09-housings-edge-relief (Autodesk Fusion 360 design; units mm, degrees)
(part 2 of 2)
sketch "B Facet 180 Triangle 4" plane through (0, -75, 0) normal (0, -1, 0) x axis (-1, 0, 0)
  line L1 (124, -27.066) -> (60.9665, 27.066)
  line L2 (124, 27.066) -> (124, -27.066)
  line L3 (60.9665, 27.066) -> (124, 27.066)
  line L4 (120, -18.3583) -> (71.7639, 23.066)
  line L5 (120, 23.066) -> (120, -18.3583)
  line L6 (71.7639, 23.066) -> (120, 23.066)
  point P1 (0, 0)
  point P2 (60.9665, 27.066)
  point P3 (124, -27.066)
  point P4 (124, 27.066)
  dimension "d486" distance P1 P2 = 60.9665 (= "Linear Dimension-2")
  dimension "d487" distance P1 P2 = 27.066 (= "Linear Dimension-3")
  dimension "d488" distance P1 P3 = 124 (= "Linear Dimension-4")
  dimension "d489" distance P1 P3 = 27.066 (= "Linear Dimension-5")
  dimension "d490" distance P1 P4 = 124 (= "Linear Dimension-6")
  dimension "d491" distance P1 P4 = 27.066 (= "Linear Dimension-7")
  dimension "d492" = -4 (= "-memberWidth / 2")
extrude "Extrude15" cut sketch "B Facet 180 Triangle 4" profile of L5 L6 L4 against normal blind 4.7 (magnitude of "-( wall + 0.2 mm )")
fillet "Fillet5" radius 1.5 (= "apertureRadius")
work_plane "WorkPlane11" RotateAngle 135 ExtraOffset 0
work_plane "WorkPlane12" AlongDistance 75 (= "bodyWidth / 2") ExtraOffset 0
sketch "B Facet 225 Triangle 1" plane through (0, -53.033, -53.033) normal (0, -0.7071, -0.7071) x axis (1, 0, 0)
  line L1 (23.9949, -27.066) -> (62.2721, 27.066)
  line L2 (0.1814, 27.066) -> (23.9949, -27.066)
  line L3 (62.2721, 27.066) -> (0.1814, 27.066)
  line L4 (24.81, -18.9852) -> (54.5447, 23.066)
  line L5 (6.311, 23.066) -> (24.81, -18.9852)
  line L6 (54.5447, 23.066) -> (6.311, 23.066)
  point P1 (0, 0)
  point P2 (62.2721, 27.066)
  point P3 (23.9949, -27.066)
  point P4 (0.1814, 27.066)
  dimension "d501" distance P1 P2 = 62.2721 (= "Linear Dimension-2")
  dimension "d502" distance P1 P2 = 27.066 (= "Linear Dimension-3")
  dimension "d503" distance P1 P3 = 23.9949 (= "Linear Dimension-4")
  dimension "d504" distance P1 P3 = 27.066 (= "Linear Dimension-5")
  dimension "d505" distance P1 P4 = 0.1814 (= "Linear Dimension-6")
  dimension "d506" distance P1 P4 = 27.066 (= "Linear Dimension-7")
  dimension "d507" = 4 (= "memberWidth / 2")
extrude "Extrude16" cut sketch "B Facet 225 Triangle 1" profile of L5 L6 L4 against normal blind 4.7 (magnitude of "-( wall + 0.2 mm )")
sketch "B Facet 225 Triangle 2" plane through (0, -53.033, -53.033) normal (0, -0.7071, -0.7071) x axis (1, 0, 0)
  line L1 (0.1814, 27.066) -> (23.9949, -27.066)
  line L2 (-74.6684, -27.066) -> (0.1814, 27.066)
  line L3 (23.9949, -27.066) -> (-74.6684, -27.066)
  line L4 (-1.4863, 20.9235) -> (17.8653, -23.066)
  line L5 (-62.3117, -23.066) -> (-1.4863, 20.9235)
  line L6 (17.8653, -23.066) -> (-62.3117, -23.066)
  point P1 (0, 0)
  point P2 (23.9949, -27.066)
  point P3 (0.1814, 27.066)
  point P4 (-74.6684, -27.066)
  dimension "d510" distance P1 P2 = 23.9949 (= "Linear Dimension-2")
  dimension "d511" distance P1 P2 = 27.066 (= "Linear Dimension-3")
  dimension "d512" distance P1 P3 = 0.1814 (= "Linear Dimension-4")
  dimension "d513" distance P1 P3 = 27.066 (= "Linear Dimension-5")
  dimension "d514" distance P1 P4 = 74.6684 (= "Linear Dimension-6")
  dimension "d515" distance P1 P4 = 27.066 (= "Linear Dimension-7")
  dimension "d516" = -4 (= "-memberWidth / 2")
extrude "Extrude17" cut sketch "B Facet 225 Triangle 2" profile of L5 L6 L4 against normal blind 4.7 (magnitude of "-( wall + 0.2 mm )")
sketch "B Facet 225 Triangle 3" plane through (0, -53.033, -53.033) normal (0, -0.7071, -0.7071) x axis (1, 0, 0)
  line L1 (-74.6684, -27.066) -> (0.1814, 27.066)
  line L2 (-124, 27.066) -> (-74.6684, -27.066)
  line L3 (0.1814, 27.066) -> (-124, 27.066)
  line L4 (-74.1179, -21.7315) -> (-12.1753, 23.066)
  line L5 (-114.9429, 23.066) -> (-74.1179, -21.7315)
  line L6 (-12.1753, 23.066) -> (-114.9429, 23.066)
  point P1 (0, 0)
  point P2 (0.1814, 27.066)
  point P3 (-74.6684, -27.066)
  point P4 (-124, 27.066)
  dimension "d519" distance P1 P2 = 0.1814 (= "Linear Dimension-2")
  dimension "d520" distance P1 P2 = 27.066 (= "Linear Dimension-3")
  dimension "d521" distance P1 P3 = 74.6684 (= "Linear Dimension-4")
  dimension "d522" distance P1 P3 = 27.066 (= "Linear Dimension-5")
  dimension "d523" distance P1 P4 = 124 (= "Linear Dimension-6")
  dimension "d524" distance P1 P4 = 27.066 (= "Linear Dimension-7")
  dimension "d525" = 4 (= "memberWidth / 2")
extrude "Extrude18" cut sketch "B Facet 225 Triangle 3" profile of L5 L6 L4 against normal blind 4.7 (magnitude of "-( wall + 0.2 mm )")
sketch "B Facet 225 Triangle 4" plane through (0, -53.033, -53.033) normal (0, -0.7071, -0.7071) x axis (1, 0, 0)
  line L1 (-124, 27.066) -> (-74.6684, -27.066)
  line L2 (-124, -27.066) -> (-124, 27.066)
  line L3 (-74.6684, -27.066) -> (-124, -27.066)
  line L4 (-120, 16.7383) -> (-83.7255, -23.066)
  line L5 (-120, -23.066) -> (-120, 16.7383)
  line L6 (-83.7255, -23.066) -> (-120, -23.066)
  point P1 (0, 0)
  point P2 (-74.6684, -27.066)
  point P3 (-124, 27.066)
  point P4 (-124, -27.066)
  dimension "d528" distance P1 P2 = 74.6684 (= "Linear Dimension-2")
  dimension "d529" distance P1 P2 = 27.066 (= "Linear Dimension-3")
  dimension "d530" distance P1 P3 = 124 (= "Linear Dimension-4")
  dimension "d531" distance P1 P3 = 27.066 (= "Linear Dimension-5")
  dimension "d532" distance P1 P4 = 124 (= "Linear Dimension-6")
  dimension "d533" distance P1 P4 = 27.066 (= "Linear Dimension-7")
  dimension "d534" = -4 (= "-memberWidth / 2")
extrude "Extrude19" cut sketch "B Facet 225 Triangle 4" profile of L5 L6 L4 against normal blind 4.7 (magnitude of "-( wall + 0.2 mm )")
fillet "Fillet6" radius 1.5 (= "apertureRadius")
work_plane "WorkPlane13" RotateAngle 180 ExtraOffset 0
work_plane "WorkPlane14" AlongDistance 75 (= "bodyWidth / 2") ExtraOffset 0
sketch "B Facet 270 Triangle 1" plane through (0, 0, -75) normal (0, 0, -1) x axis (-1, 0, 0)
  line L1 (36.9655, 27.066) -> (-17.1665, -27.066)
  line L2 (53.4167, -27.066) -> (36.9655, 27.066)
  line L3 (-17.1665, -27.066) -> (53.4167, -27.066)
  line L4 (35.0777, 19.5214) -> (-7.5097, -23.066)
  line L5 (48.0205, -23.066) -> (35.0777, 19.5214)
  line L6 (-7.5097, -23.066) -> (48.0205, -23.066)
  point P1 (0, 0)
  point P2 (-17.1665, -27.066)
  point P3 (36.9655, 27.066)
  point P4 (53.4167, -27.066)
  dimension "d543" distance P1 P2 = 17.1665 (= "Linear Dimension-2")
  dimension "d544" distance P1 P2 = 27.066 (= "Linear Dimension-3")
  dimension "d545" distance P1 P3 = 36.9655 (= "Linear Dimension-4")
  dimension "d546" distance P1 P3 = 27.066 (= "Linear Dimension-5")
  dimension "d547" distance P1 P4 = 53.4167 (= "Linear Dimension-6")
  dimension "d548" distance P1 P4 = 27.066 (= "Linear Dimension-7")
  dimension "d549" = 4 (= "memberWidth / 2")
extrude "Extrude20" cut sketch "B Facet 270 Triangle 1" profile of L5 L6 L4 against normal blind 4.7 (magnitude of "-( wall + 0.2 mm )")
sketch "B Facet 270 Triangle 2" plane through (0, 0, -75) normal (0, 0, -1) x axis (-1, 0, 0)
  line L1 (53.4167, -27.066) -> (36.9655, 27.066)
  line L2 (124, 27.066) -> (53.4167, -27.066)
  line L3 (36.9655, 27.066) -> (124, 27.066)
  line L4 (55.5648, -20.3777) -> (42.3618, 23.066)
  line L5 (112.2115, 23.066) -> (55.5648, -20.3777)
  line L6 (42.3618, 23.066) -> (112.2115, 23.066)
  point P1 (0, 0)
  point P2 (36.9655, 27.066)
  point P3 (53.4167, -27.066)
  point P4 (124, 27.066)
  dimension "d552" distance P1 P2 = 36.9655 (= "Linear Dimension-2")
  dimension "d553" distance P1 P2 = 27.066 (= "Linear Dimension-3")
  dimension "d554" distance P1 P3 = 53.4167 (= "Linear Dimension-4")
  dimension "d555" distance P1 P3 = 27.066 (= "Linear Dimension-5")
  dimension "d556" distance P1 P4 = 124 (= "Linear Dimension-6")
  dimension "d557" distance P1 P4 = 27.066 (= "Linear Dimension-7")
  dimension "d558" = -4 (= "-memberWidth / 2")
extrude "Extrude21" cut sketch "B Facet 270 Triangle 2" profile of L5 L6 L4 against normal blind 4.7 (magnitude of "-( wall + 0.2 mm )")
sketch "B Facet 270 Triangle 3" plane through (0, 0, -75) normal (0, 0, -1) x axis (-1, 0, 0)
  line L1 (124, 27.066) -> (53.4167, -27.066)
  line L2 (124, -27.066) -> (124, 27.066)
  line L3 (53.4167, -27.066) -> (124, -27.066)
  line L4 (120, 18.9574) -> (65.2053, -23.066)
  line L5 (120, -23.066) -> (120, 18.9574)
  line L6 (65.2053, -23.066) -> (120, -23.066)
  point P1 (0, 0)
  point P2 (53.4167, -27.066)
  point P3 (124, 27.066)
  point P4 (124, -27.066)
  dimension "d561" distance P1 P2 = 53.4167 (= "Linear Dimension-2")
  dimension "d562" distance P1 P2 = 27.066 (= "Linear Dimension-3")
  dimension "d563" distance P1 P3 = 124 (= "Linear Dimension-4")
  dimension "d564" distance P1 P3 = 27.066 (= "Linear Dimension-5")
  dimension "d565" distance P1 P4 = 124 (= "Linear Dimension-6")
  dimension "d566" distance P1 P4 = 27.066 (= "Linear Dimension-7")
  dimension "d567" = 4 (= "memberWidth / 2")
extrude "Extrude22" cut sketch "B Facet 270 Triangle 3" profile of L5 L6 L4 against normal blind 4.7 (magnitude of "-( wall + 0.2 mm )")
fillet "Fillet7" radius 1.5 (= "apertureRadius")
work_plane "WorkPlane15" RotateAngle 225 ExtraOffset 0
work_plane "WorkPlane16" AlongDistance 75 (= "bodyWidth / 2") ExtraOffset 0
sketch "B Facet 315 Triangle 1" plane through (0, 53.033, -53.033) normal (0, 0.7071, -0.7071) x axis (1, 0, 0)
  line L1 (-82.0711, -27.066) -> (-43.7939, 27.066)
  line L2 (-124, 27.066) -> (-82.0711, -27.066)
  line L3 (-43.7939, 27.066) -> (-124, 27.066)
  line L4 (-82.2175, -20.3449) -> (-51.5213, 23.066)
  line L5 (-115.8422, 23.066) -> (-82.2175, -20.3449)
  line L6 (-51.5213, 23.066) -> (-115.8422, 23.066)
  point P1 (0, 0)
  point P2 (-43.7939, 27.066)
  point P3 (-82.0711, -27.066)
  point P4 (-124, 27.066)
  dimension "d576" distance P1 P2 = 43.7939 (= "Linear Dimension-2")
  dimension "d577" distance P1 P2 = 27.066 (= "Linear Dimension-3")
  dimension "d578" distance P1 P3 = 82.0711 (= "Linear Dimension-4")
  dimension "d579" distance P1 P3 = 27.066 (= "Linear Dimension-5")
  dimension "d580" distance P1 P4 = 124 (= "Linear Dimension-6")
  dimension "d581" distance P1 P4 = 27.066 (= "Linear Dimension-7")
  dimension "d582" = 4 (= "memberWidth / 2")
extrude "Extrude23" cut sketch "B Facet 315 Triangle 1" profile of L5 L6 L4 against normal blind 4.7 (magnitude of "-( wall + 0.2 mm )")
sketch "B Facet 315 Triangle 2" plane through (0, 53.033, -53.033) normal (0, 0.7071, -0.7071) x axis (1, 0, 0)
  line L1 (-124, 27.066) -> (-82.0711, -27.066)
  line L2 (-124, -27.066) -> (-124, 27.066)
  line L3 (-82.0711, -27.066) -> (-124, -27.066)
  line L4 (-120, 15.3697) -> (-90.2289, -23.066)
  line L5 (-120, -23.066) -> (-120, 15.3697)
  line L6 (-90.2289, -23.066) -> (-120, -23.066)
  point P1 (0, 0)
  point P2 (-82.0711, -27.066)
  point P3 (-124, 27.066)
  point P4 (-124, -27.066)
  dimension "d585" distance P1 P2 = 82.0711 (= "Linear Dimension-2")
  dimension "d586" distance P1 P2 = 27.066 (= "Linear Dimension-3")
  dimension "d587" distance P1 P3 = 124 (= "Linear Dimension-4")
  dimension "d588" distance P1 P3 = 27.066 (= "Linear Dimension-5")
  dimension "d589" distance P1 P4 = 124 (= "Linear Dimension-6")
  dimension "d590" distance P1 P4 = 27.066 (= "Linear Dimension-7")
  dimension "d591" = -4 (= "-memberWidth / 2")
extrude "Extrude24" cut sketch "B Facet 315 Triangle 2" profile of L5 L6 L4 against normal blind 4.7 (magnitude of "-( wall + 0.2 mm )")
fillet "Fillet8" radius 1.5 (= "apertureRadius")
work_plane "WorkPlane17" AlongDistance 0.5 (= "qFront") ExtraOffset 0
sketch "A Central Carrier sketch" plane through (0.3536, 0.3536, 0) normal (0.7071, 0.7071, 0) x axis (0, 0, 1)
  circle C1 centre (0, 0) radius 26
  dimension "d598" diameter C1 = 52 (= "carrierOD")
extrude "Extrude25" new body sketch "A Central Carrier sketch" along normal blind 18 (= "spokeDepth")
work_plane "WorkPlane18" AlongDistance 0.5 (= "qFront") ExtraOffset 0
sketch "A Spoke 1 Profile" plane through (0.3536, 0.3536, 0) normal (0.7071, 0.7071, 0) x axis (0, 0, 1)
  line L1 (37.3643, -145.3579) -> (-4.7984, -1.4054)
  line L2 (46.9611, -142.547) -> (37.3643, -145.3579)
  line L3 (4.7984, 1.4054) -> (46.9611, -142.547)
  line L4 (-4.7984, -1.4054) -> (4.7984, 1.4054)
  point P1 (0, 0)
  point P2 (-4.7984, -1.4054)
  point P3 (37.3643, -145.3579)
  point P4 (46.9611, -142.547)
  point P5 (4.7984, 1.4054)
  dimension "d603" distance P1 P2 = 4.7984 (= "Linear Dimension-2")
  dimension "d604" distance P1 P2 = 1.4054 (= "Linear Dimension-3")
  dimension "d605" distance P1 P3 = 37.3643 (= "Linear Dimension-4")
  dimension "d606" distance P1 P3 = 145.3579 (= "Linear Dimension-5")
  dimension "d607" distance P1 P4 = 46.9611 (= "Linear Dimension-6")
  dimension "d608" distance P1 P4 = 142.547 (= "Linear Dimension-7")
  dimension "d609" distance P1 P5 = 4.7984 (= "Linear Dimension-8")
  dimension "d610" distance P1 P5 = 1.4054 (= "Linear Dimension-9")
extrude "Extrude26" add sketch "A Spoke 1 Profile" along normal blind 18 (= "spokeDepth")
sketch "A Spoke 2 Profile" plane through (0.3536, 0.3536, 0) normal (0.7071, 0.7071, 0) x axis (0, 0, 1)
  line L1 (126.9012, -80.1317) -> (-2.5272, -4.3143)
  line L2 (131.9557, -71.5031) -> (126.9012, -80.1317)
  line L3 (2.5272, 4.3143) -> (131.9557, -71.5031)
  line L4 (-2.5272, -4.3143) -> (2.5272, 4.3143)
  point P1 (0, 0)
  point P2 (-2.5272, -4.3143)
  point P3 (126.9012, -80.1317)
  point P4 (131.9557, -71.5031)
  point P5 (2.5272, 4.3143)
  dimension "d613" distance P1 P2 = 2.5272 (= "Linear Dimension-2")
  dimension "d614" distance P1 P2 = 4.3143 (= "Linear Dimension-3")
  dimension "d615" distance P1 P3 = 126.9012 (= "Linear Dimension-4")
  dimension "d616" distance P1 P3 = 80.1317 (= "Linear Dimension-5")
  dimension "d617" distance P1 P4 = 131.9557 (= "Linear Dimension-6")
  dimension "d618" distance P1 P4 = 71.5031 (= "Linear Dimension-7")
  dimension "d619" distance P1 P5 = 2.5272 (= "Linear Dimension-8")
  dimension "d620" distance P1 P5 = 4.3143 (= "Linear Dimension-9")
extrude "Extrude27" add sketch "A Spoke 2 Profile" along normal blind 18 (= "spokeDepth")
sketch "A Spoke 3 Profile" plane through (0.3536, 0.3536, 0) normal (0.7071, 0.7071, 0) x axis (0, 0, 1)
  line L1 (131.9557, 71.5031) -> (2.5272, -4.3143)
  line L2 (126.9012, 80.1317) -> (131.9557, 71.5031)
  line L3 (-2.5272, 4.3143) -> (126.9012, 80.1317)
  line L4 (2.5272, -4.3143) -> (-2.5272, 4.3143)
  point P1 (0, 0)
  point P2 (2.5272, -4.3143)
  point P3 (131.9557, 71.5031)
  point P4 (126.9012, 80.1317)
  point P5 (-2.5272, 4.3143)
  dimension "d623" distance P1 P2 = 2.5272 (= "Linear Dimension-2")
  dimension "d624" distance P1 P2 = 4.3143 (= "Linear Dimension-3")
  dimension "d625" distance P1 P3 = 131.9557 (= "Linear Dimension-4")
  dimension "d626" distance P1 P3 = 71.5031 (= "Linear Dimension-5")
  dimension "d627" distance P1 P4 = 126.9012 (= "Linear Dimension-6")
  dimension "d628" distance P1 P4 = 80.1317 (= "Linear Dimension-7")
  dimension "d629" distance P1 P5 = 2.5272 (= "Linear Dimension-8")
  dimension "d630" distance P1 P5 = 4.3143 (= "Linear Dimension-9")
extrude "Extrude28" add sketch "A Spoke 3 Profile" along normal blind 18 (= "spokeDepth")
sketch "A Spoke 4 Profile" plane through (0.3536, 0.3536, 0) normal (0.7071, 0.7071, 0) x axis (0, 0, 1)
  line L1 (46.9611, 142.547) -> (4.7984, -1.4054)
  line L2 (37.3643, 145.3579) -> (46.9611, 142.547)
  line L3 (-4.7984, 1.4054) -> (37.3643, 145.3579)
  line L4 (4.7984, -1.4054) -> (-4.7984, 1.4054)
  point P1 (0, 0)
  point P2 (4.7984, -1.4054)
  point P3 (46.9611, 142.547)
  point P4 (37.3643, 145.3579)
  point P5 (-4.7984, 1.4054)
  dimension "d633" distance P1 P2 = 4.7984 (= "Linear Dimension-2")
  dimension "d634" distance P1 P2 = 1.4054 (= "Linear Dimension-3")
  dimension "d635" distance P1 P3 = 46.9611 (= "Linear Dimension-4")
  dimension "d636" distance P1 P3 = 142.547 (= "Linear Dimension-5")
  dimension "d637" distance P1 P4 = 37.3643 (= "Linear Dimension-6")
  dimension "d638" distance P1 P4 = 145.3579 (= "Linear Dimension-7")
  dimension "d639" distance P1 P5 = 4.7984 (= "Linear Dimension-8")
  dimension "d640" distance P1 P5 = 1.4054 (= "Linear Dimension-9")
extrude "Extrude29" add sketch "A Spoke 4 Profile" along normal blind 18 (= "spokeDepth")
sketch "A Spoke 5 Profile" plane through (0.3536, 0.3536, 0) normal (0.7071, 0.7071, 0) x axis (0, 0, 1)
  line L1 (-37.3643, 145.3579) -> (4.7984, 1.4054)
  line L2 (-46.9611, 142.547) -> (-37.3643, 145.3579)
  line L3 (-4.7984, -1.4054) -> (-46.9611, 142.547)
  line L4 (4.7984, 1.4054) -> (-4.7984, -1.4054)
  point P1 (0, 0)
  point P2 (4.7984, 1.4054)
  point P3 (-37.3643, 145.3579)
  point P4 (-46.9611, 142.547)
  point P5 (-4.7984, -1.4054)
  dimension "d643" distance P1 P2 = 4.7984 (= "Linear Dimension-2")
  dimension "d644" distance P1 P2 = 1.4054 (= "Linear Dimension-3")
  dimension "d645" distance P1 P3 = 37.3643 (= "Linear Dimension-4")
  dimension "d646" distance P1 P3 = 145.3579 (= "Linear Dimension-5")
  dimension "d647" distance P1 P4 = 46.9611 (= "Linear Dimension-6")
  dimension "d648" distance P1 P4 = 142.547 (= "Linear Dimension-7")
  dimension "d649" distance P1 P5 = 4.7984 (= "Linear Dimension-8")
  dimension "d650" distance P1 P5 = 1.4054 (= "Linear Dimension-9")
extrude "Extrude30" add sketch "A Spoke 5 Profile" along normal blind 18 (= "spokeDepth")
sketch "A Spoke 6 Profile" plane through (0.3536, 0.3536, 0) normal (0.7071, 0.7071, 0) x axis (0, 0, 1)
  line L1 (-126.9012, 80.1317) -> (2.5272, 4.3143)
  line L2 (-131.9557, 71.5031) -> (-126.9012, 80.1317)
  line L3 (-2.5272, -4.3143) -> (-131.9557, 71.5031)
  line L4 (2.5272, 4.3143) -> (-2.5272, -4.3143)
  point P1 (0, 0)
  point P2 (2.5272, 4.3143)
  point P3 (-126.9012, 80.1317)
  point P4 (-131.9557, 71.5031)
  point P5 (-2.5272, -4.3143)
  dimension "d653" distance P1 P2 = 2.5272 (= "Linear Dimension-2")
  dimension "d654" distance P1 P2 = 4.3143 (= "Linear Dimension-3")
  dimension "d655" distance P1 P3 = 126.9012 (= "Linear Dimension-4")
  dimension "d656" distance P1 P3 = 80.1317 (= "Linear Dimension-5")
  dimension "d657" distance P1 P4 = 131.9557 (= "Linear Dimension-6")
  dimension "d658" distance P1 P4 = 71.5031 (= "Linear Dimension-7")
  dimension "d659" distance P1 P5 = 2.5272 (= "Linear Dimension-8")
  dimension "d660" distance P1 P5 = 4.3143 (= "Linear Dimension-9")
extrude "Extrude31" add sketch "A Spoke 6 Profile" along normal blind 18 (= "spokeDepth")
sketch "A Spoke 7 Profile" plane through (0.3536, 0.3536, 0) normal (0.7071, 0.7071, 0) x axis (0, 0, 1)
  line L1 (-131.9557, -71.5031) -> (-2.5272, 4.3143)
  line L2 (-126.9012, -80.1317) -> (-131.9557, -71.5031)
  line L3 (2.5272, -4.3143) -> (-126.9012, -80.1317)
  line L4 (-2.5272, 4.3143) -> (2.5272, -4.3143)
  point P1 (0, 0)
  point P2 (-2.5272, 4.3143)
  point P3 (-131.9557, -71.5031)
  point P4 (-126.9012, -80.1317)
  point P5 (2.5272, -4.3143)
  dimension "d663" distance P1 P2 = 2.5272 (= "Linear Dimension-2")
  dimension "d664" distance P1 P2 = 4.3143 (= "Linear Dimension-3")
  dimension "d665" distance P1 P3 = 131.9557 (= "Linear Dimension-4")
  dimension "d666" distance P1 P3 = 71.5031 (= "Linear Dimension-5")
  dimension "d667" distance P1 P4 = 126.9012 (= "Linear Dimension-6")
  dimension "d668" distance P1 P4 = 80.1317 (= "Linear Dimension-7")
  dimension "d669" distance P1 P5 = 2.5272 (= "Linear Dimension-8")
  dimension "d670" distance P1 P5 = 4.3143 (= "Linear Dimension-9")
extrude "Extrude32" add sketch "A Spoke 7 Profile" along normal blind 18 (= "spokeDepth")
sketch "A Spoke 8 Profile" plane through (0.3536, 0.3536, 0) normal (0.7071, 0.7071, 0) x axis (0, 0, 1)
  line L1 (-46.9611, -142.547) -> (-4.7984, 1.4054)
  line L2 (-37.3643, -145.3579) -> (-46.9611, -142.547)
  line L3 (4.7984, 1.4054) -> (-37.3643, -145.3579)
  line L4 (-4.7984, 1.4054) -> (4.7984, 1.4054)
  point P1 (0, 0)
  point P2 (-4.7984, 1.4054)
  point P3 (-46.9611, -142.547)
  point P4 (-37.3643, -145.3579)
  point P5 (4.7984, 1.4054)
  dimension "d673" distance P1 P2 = 4.7984 (= "Linear Dimension-2")
  dimension "d674" distance P1 P2 = 1.4054 (= "Linear Dimension-3")
  dimension "d675" distance P1 P3 = 46.9611 (= "Linear Dimension-4")
  dimension "d676" distance P1 P3 = 142.547 (= "Linear Dimension-5")
  dimension "d677" distance P1 P4 = 37.3643 (= "Linear Dimension-6")
  dimension "d678" distance P1 P4 = 145.3579 (= "Linear Dimension-7")
  dimension "d679" distance P1 P5 = 4.7984 (= "Linear Dimension-8")
  dimension "d680" distance P1 P5 = 1.4054 (= "Linear Dimension-9")
extrude "Extrude33" add sketch "A Spoke 8 Profile" along normal blind 18 (= "spokeDepth")
sketch "Spoke Outer Envelope" plane through (0, 0, 0) normal (1, 0, 0) x axis (0, 0, -1)
  line L1 (31.066, 75) -> (75, 31.066)
  line L2 (-31.066, 75) -> (31.066, 75)
  line L3 (-75, 31.066) -> (-31.066, 75)
  line L4 (-75, -31.066) -> (-75, 31.066)
  line L5 (-31.066, -75) -> (-75, -31.066)
  line L6 (31.066, -75) -> (-31.066, -75)
  line L7 (75, -31.066) -> (31.066, -75)
  line L8 (75, 31.066) -> (75, -31.066)
  point P1 (0, 0)
  point P10 (0, 0)
  point P3 (31.066, 75)
  point P8 (31.066, -75)
  coincident P1 P10
  horizontal L2
  dimension "d683" distance P3 P8 = 150 (= "bodyWidth")
extrude "Extrude34" sketch "Spoke Outer Envelope" distance 260 (= "bodyLength")
fillet "Fillet9" radius 1 (= "rootRadius")
work_plane "WorkPlane19" AlongDistance 10.6 (= "qFrontBack") ExtraOffset 0
sketch "A Rear Carrier Clearance sketch" plane through (7.4953, 7.4953, 0) normal (0.7071, 0.7071, 0) x axis (0, 0, 1)
  circle C1 centre (0, 0) radius 23
  dimension "d690" diameter C1 = 46 (= "rearCarrierClearance")
extrude "Extrude35" cut sketch "A Rear Carrier Clearance sketch" along normal blind 18 (= "spokeDepth")
work_plane "WorkPlane20" AlongDistance 0.5 (= "qFront") ExtraOffset 0
sketch "A Seal Relief sketch" plane through (0.3536, 0.3536, 0) normal (0.7071, 0.7071, 0) x axis (0, 0, 1)
  circle C1 centre (0, 0) radius 9.75
  dimension "d695" diameter C1 = 19.5 (= "raceRelief")
extrude "Extrude36" cut sketch "A Seal Relief sketch" along normal blind 10.1 (= "frontSeatDepth + shoulder")
work_plane "WorkPlane21" AlongDistance 0.5 (= "qFront") ExtraOffset 0
sketch "A Front Bearing Seat sketch" plane through (0.3536, 0.3536, 0) normal (0.7071, 0.7071, 0) x axis (0, 0, 1)
  circle C1 centre (0, 0) radius 11.1
  dimension "d700" diameter C1 = 22.2 (= "seatDiameter")
extrude "Extrude37" cut sketch "A Front Bearing Seat sketch" along normal blind 7.1 (= "frontSeatDepth")
work_plane "WorkPlane22" AlongDistance 0.5 (= "qFront") ExtraOffset 0
sketch "A Support Bolt seed" plane through (0.3536, 0.3536, 0) normal (0.7071, 0.7071, 0) x axis (0, 0, 1)
  line L1 (17, 0) -> (0, 0)
  circle C1 centre (17, 0) radius 1.65
  point P1 (0, 0)
  point P2 (17, 0)
  horizontal L1
  dimension "d705" distance P1 P2 = 17 (= "supportCircle / 2")
  dimension "d706" diameter C1 = 3.3 (= "m3Clearance")
extrude "Extrude38" cut sketch "A Support Bolt seed" profile of C1 along normal blind 10.1 (= "frontSeatDepth + shoulder")
circular_pattern "C-Pattern1" TotalAngle 360
work_plane "WorkPlane23" AlongDistance 0.5 (= "qFront") ExtraOffset 0
sketch "A Front Bearing Boss sketch" plane through (0.3536, 0.3536, 0) normal (0.7071, 0.7071, 0) x axis (0, 0, 1)
  circle C1 centre (0, 0) radius 22
  dimension "d713" diameter C1 = 44 (= "coreOD")
chamfer "Chamfer1" distance 0.4 (= "entryChamfer")
work_plane "WorkPlane24" AlongDistance 75 (= "bodyWidth / 2") ExtraOffset 0
sketch "A Collar Driver Corridors" plane through (0, 0, 75) normal (0, 0, 1) x axis (1, 0, 0)
  circle C1 centre (6.7175, 15.9099) radius 3
  circle C2 centre (15.9099, 6.7175) radius 3
  point P1 (0, 0)
  point P2 (6.7175, 15.9099)
  point P3 (15.9099, 6.7175)
  dimension "d717" distance P1 P2 = 6.7175 (= "abs(( 16 mm + ( -6.5 mm ) ) / sqrt(2))")
  dimension "d718" distance P1 P2 = 15.9099 (= "abs(( 16 mm - ( -6.5 mm ) ) / sqrt(2))")
  dimension "d719" diameter C1 = 6
  dimension "d720" distance P1 P3 = 15.9099 (= "abs(( 16 mm + ( 6.5 mm ) ) / sqrt(2))")
  dimension "d721" distance P1 P3 = 6.7175 (= "abs(( 16 mm - ( 6.5 mm ) ) / sqrt(2))")
  dimension "d722" diameter C2 = 6
extrude "Extrude39" cut sketch "A Collar Driver Corridors" against normal blind 75 (magnitude of "-( bodyWidth / 2 )")
work_plane "WorkPlane17" ExtraOffset 0
sketch "B Central Carrier sketch" plane through (-0.3536, -0.3536, 0) normal (0.7071, 0.7071, 0) x axis (0, 0, 1)
  circle C1 centre (0, 0) radius 38
  dimension "d727" diameter C1 = 76 (= "mountOD")
extrude "Extrude25" new body sketch "B Central Carrier sketch" no distance stored
work_plane "WorkPlane18" ExtraOffset 0
sketch "B Spoke 1 Profile" plane through (-0.3536, -0.3536, 0) normal (0.7071, 0.7071, 0) x axis (0, 0, 1)
  line L1 (37.3643, -145.3579) -> (-4.7984, -1.4054)
  line L2 (46.9611, -142.547) -> (37.3643, -145.3579)
  line L3 (4.7984, 1.4054) -> (46.9611, -142.547)
  line L4 (-4.7984, -1.4054) -> (4.7984, 1.4054)
  point P1 (0, 0)
  point P2 (-4.7984, -1.4054)
  point P3 (37.3643, -145.3579)
  point P4 (46.9611, -142.547)
  point P5 (4.7984, 1.4054)
  dimension "d732" distance P1 P2 = 4.7984 (= "Linear Dimension-2")
  dimension "d733" distance P1 P2 = 1.4054 (= "Linear Dimension-3")
  dimension "d734" distance P1 P3 = 37.3643 (= "Linear Dimension-4")
  dimension "d735" distance P1 P3 = 145.3579 (= "Linear Dimension-5")
  dimension "d736" distance P1 P4 = 46.9611 (= "Linear Dimension-6")
  dimension "d737" distance P1 P4 = 142.547 (= "Linear Dimension-7")
  dimension "d738" distance P1 P5 = 4.7984 (= "Linear Dimension-8")
  dimension "d739" distance P1 P5 = 1.4054 (= "Linear Dimension-9")
extrude "Extrude26" add sketch "B Spoke 1 Profile" no distance stored
sketch "B Spoke 2 Profile" plane through (-0.3536, -0.3536, 0) normal (0.7071, 0.7071, 0) x axis (0, 0, 1)
  line L1 (126.9012, -80.1317) -> (-2.5272, -4.3143)
  line L2 (131.9557, -71.5031) -> (126.9012, -80.1317)
  line L3 (2.5272, 4.3143) -> (131.9557, -71.5031)
  line L4 (-2.5272, -4.3143) -> (2.5272, 4.3143)
  point P1 (0, 0)
  point P2 (-2.5272, -4.3143)
  point P3 (126.9012, -80.1317)
  point P4 (131.9557, -71.5031)
  point P5 (2.5272, 4.3143)
  dimension "d742" distance P1 P2 = 2.5272 (= "Linear Dimension-2")
  dimension "d743" distance P1 P2 = 4.3143 (= "Linear Dimension-3")
  dimension "d744" distance P1 P3 = 126.9012 (= "Linear Dimension-4")
  dimension "d745" distance P1 P3 = 80.1317 (= "Linear Dimension-5")
  dimension "d746" distance P1 P4 = 131.9557 (= "Linear Dimension-6")
  dimension "d747" distance P1 P4 = 71.5031 (= "Linear Dimension-7")
  dimension "d748" distance P1 P5 = 2.5272 (= "Linear Dimension-8")
  dimension "d749" distance P1 P5 = 4.3143 (= "Linear Dimension-9")
extrude "Extrude27" add sketch "B Spoke 2 Profile" no distance stored
sketch "B Spoke 3 Profile" plane through (-0.3536, -0.3536, 0) normal (0.7071, 0.7071, 0) x axis (0, 0, 1)
  line L1 (131.9557, 71.5031) -> (2.5272, -4.3143)
  line L2 (126.9012, 80.1317) -> (131.9557, 71.5031)
  line L3 (-2.5272, 4.3143) -> (126.9012, 80.1317)
  line L4 (2.5272, -4.3143) -> (-2.5272, 4.3143)
  point P1 (0, 0)
  point P2 (2.5272, -4.3143)
  point P3 (131.9557, 71.5031)
  point P4 (126.9012, 80.1317)
  point P5 (-2.5272, 4.3143)
  dimension "d752" distance P1 P2 = 2.5272 (= "Linear Dimension-2")
  dimension "d753" distance P1 P2 = 4.3143 (= "Linear Dimension-3")
  dimension "d754" distance P1 P3 = 131.9557 (= "Linear Dimension-4")
  dimension "d755" distance P1 P3 = 71.5031 (= "Linear Dimension-5")
  dimension "d756" distance P1 P4 = 126.9012 (= "Linear Dimension-6")
  dimension "d757" distance P1 P4 = 80.1317 (= "Linear Dimension-7")
  dimension "d758" distance P1 P5 = 2.5272 (= "Linear Dimension-8")
  dimension "d759" distance P1 P5 = 4.3143 (= "Linear Dimension-9")
extrude "Extrude28" add sketch "B Spoke 3 Profile" no distance stored
sketch "B Spoke 4 Profile" plane through (-0.3536, -0.3536, 0) normal (0.7071, 0.7071, 0) x axis (0, 0, 1)
  line L1 (46.9611, 142.547) -> (4.7984, -1.4054)
  line L2 (37.3643, 145.3579) -> (46.9611, 142.547)
  line L3 (-4.7984, 1.4054) -> (37.3643, 145.3579)
  line L4 (4.7984, -1.4054) -> (-4.7984, 1.4054)
  point P1 (0, 0)
  point P2 (4.7984, -1.4054)
  point P3 (46.9611, 142.547)
  point P4 (37.3643, 145.3579)
  point P5 (-4.7984, 1.4054)
  dimension "d762" distance P1 P2 = 4.7984 (= "Linear Dimension-2")
  dimension "d763" distance P1 P2 = 1.4054 (= "Linear Dimension-3")
  dimension "d764" distance P1 P3 = 46.9611 (= "Linear Dimension-4")
  dimension "d765" distance P1 P3 = 142.547 (= "Linear Dimension-5")
  dimension "d766" distance P1 P4 = 37.3643 (= "Linear Dimension-6")
  dimension "d767" distance P1 P4 = 145.3579 (= "Linear Dimension-7")
  dimension "d768" distance P1 P5 = 4.7984 (= "Linear Dimension-8")
  dimension "d769" distance P1 P5 = 1.4054 (= "Linear Dimension-9")
extrude "Extrude29" add sketch "B Spoke 4 Profile" no distance stored
sketch "B Spoke 5 Profile" plane through (-0.3536, -0.3536, 0) normal (0.7071, 0.7071, 0) x axis (0, 0, 1)
  line L1 (-37.3643, 145.3579) -> (4.7984, 1.4054)
  line L2 (-46.9611, 142.547) -> (-37.3643, 145.3579)
  line L3 (-4.7984, -1.4054) -> (-46.9611, 142.547)
  line L4 (4.7984, 1.4054) -> (-4.7984, -1.4054)
  point P1 (0, 0)
  point P2 (4.7984, 1.4054)
  point P3 (-37.3643, 145.3579)
  point P4 (-46.9611, 142.547)
  point P5 (-4.7984, -1.4054)
  dimension "d772" distance P1 P2 = 4.7984 (= "Linear Dimension-2")
  dimension "d773" distance P1 P2 = 1.4054 (= "Linear Dimension-3")
  dimension "d774" distance P1 P3 = 37.3643 (= "Linear Dimension-4")
  dimension "d775" distance P1 P3 = 145.3579 (= "Linear Dimension-5")
  dimension "d776" distance P1 P4 = 46.9611 (= "Linear Dimension-6")
  dimension "d777" distance P1 P4 = 142.547 (= "Linear Dimension-7")
  dimension "d778" distance P1 P5 = 4.7984 (= "Linear Dimension-8")
  dimension "d779" distance P1 P5 = 1.4054 (= "Linear Dimension-9")
extrude "Extrude30" add sketch "B Spoke 5 Profile" no distance stored
sketch "B Spoke 6 Profile" plane through (-0.3536, -0.3536, 0) normal (0.7071, 0.7071, 0) x axis (0, 0, 1)
  line L1 (-126.9012, 80.1317) -> (2.5272, 4.3143)
  line L2 (-131.9557, 71.5031) -> (-126.9012, 80.1317)
  line L3 (-2.5272, -4.3143) -> (-131.9557, 71.5031)
  line L4 (2.5272, 4.3143) -> (-2.5272, -4.3143)
  point P1 (0, 0)
  point P2 (2.5272, 4.3143)
  point P3 (-126.9012, 80.1317)
  point P4 (-131.9557, 71.5031)
  point P5 (-2.5272, -4.3143)
  dimension "d782" distance P1 P2 = 2.5272 (= "Linear Dimension-2")
  dimension "d783" distance P1 P2 = 4.3143 (= "Linear Dimension-3")
  dimension "d784" distance P1 P3 = 126.9012 (= "Linear Dimension-4")
  dimension "d785" distance P1 P3 = 80.1317 (= "Linear Dimension-5")
  dimension "d786" distance P1 P4 = 131.9557 (= "Linear Dimension-6")
  dimension "d787" distance P1 P4 = 71.5031 (= "Linear Dimension-7")
  dimension "d788" distance P1 P5 = 2.5272 (= "Linear Dimension-8")
  dimension "d789" distance P1 P5 = 4.3143 (= "Linear Dimension-9")
extrude "Extrude31" add sketch "B Spoke 6 Profile" no distance stored
sketch "B Spoke 7 Profile" plane through (-0.3536, -0.3536, 0) normal (0.7071, 0.7071, 0) x axis (0, 0, 1)
  line L1 (-131.9557, -71.5031) -> (-2.5272, 4.3143)
  line L2 (-126.9012, -80.1317) -> (-131.9557, -71.5031)
  line L3 (2.5272, -4.3143) -> (-126.9012, -80.1317)
  line L4 (-2.5272, 4.3143) -> (2.5272, -4.3143)
  point P1 (0, 0)
  point P2 (-2.5272, 4.3143)
  point P3 (-131.9557, -71.5031)
  point P4 (-126.9012, -80.1317)
  point P5 (2.5272, -4.3143)
  dimension "d792" distance P1 P2 = 2.5272 (= "Linear Dimension-2")
  dimension "d793" distance P1 P2 = 4.3143 (= "Linear Dimension-3")
  dimension "d794" distance P1 P3 = 131.9557 (= "Linear Dimension-4")
  dimension "d795" distance P1 P3 = 71.5031 (= "Linear Dimension-5")
  dimension "d796" distance P1 P4 = 126.9012 (= "Linear Dimension-6")
  dimension "d797" distance P1 P4 = 80.1317 (= "Linear Dimension-7")
  dimension "d798" distance P1 P5 = 2.5272 (= "Linear Dimension-8")
  dimension "d799" distance P1 P5 = 4.3143 (= "Linear Dimension-9")
extrude "Extrude32" add sketch "B Spoke 7 Profile" no distance stored
sketch "B Spoke 8 Profile" plane through (-0.3536, -0.3536, 0) normal (0.7071, 0.7071, 0) x axis (0, 0, 1)
  line L1 (-46.9611, -142.547) -> (-4.7984, 1.4054)
  line L2 (-37.3643, -145.3579) -> (-46.9611, -142.547)
  line L3 (4.7984, 1.4054) -> (-37.3643, -145.3579)
  line L4 (-4.7984, 1.4054) -> (4.7984, 1.4054)
  point P1 (0, 0)
  point P2 (-4.7984, 1.4054)
  point P3 (-46.9611, -142.547)
  point P4 (-37.3643, -145.3579)
  point P5 (4.7984, 1.4054)
  dimension "d802" distance P1 P2 = 4.7984 (= "Linear Dimension-2")
  dimension "d803" distance P1 P2 = 1.4054 (= "Linear Dimension-3")
  dimension "d804" distance P1 P3 = 46.9611 (= "Linear Dimension-4")
  dimension "d805" distance P1 P3 = 142.547 (= "Linear Dimension-5")
  dimension "d806" distance P1 P4 = 37.3643 (= "Linear Dimension-6")
  dimension "d807" distance P1 P4 = 145.3579 (= "Linear Dimension-7")
  dimension "d808" distance P1 P5 = 4.7984 (= "Linear Dimension-8")
  dimension "d809" distance P1 P5 = 1.4054 (= "Linear Dimension-9")
extrude "Extrude33" add sketch "B Spoke 8 Profile" no distance stored
sketch "Spoke Outer Envelope" plane through (0, 0, 0) normal (1, 0, 0) x axis (0, 0, -1)
  line L1 (31.066, 75) -> (75, 31.066)
  line L2 (-31.066, 75) -> (31.066, 75)
  line L3 (-75, 31.066) -> (-31.066, 75)
  line L4 (-75, -31.066) -> (-75, 31.066)
  line L5 (-31.066, -75) -> (-75, -31.066)
  line L6 (31.066, -75) -> (-31.066, -75)
  line L7 (75, -31.066) -> (31.066, -75)
  line L8 (75, 31.066) -> (75, -31.066)
  point P1 (0, 0)
  point P10 (0, 0)
  point P3 (31.066, 75)
  point P8 (31.066, -75)
  coincident P1 P10
  horizontal L2
  dimension "d812" distance P3 P8 = 150 (= "bodyWidth")
extrude "Extrude34" sketch "Spoke Outer Envelope" distance 260 (= "bodyLength")
fillet "Fillet9" radius 1 (= "rootRadius")
work_plane "WorkPlane19" ExtraOffset 0
sketch "B Open Hub Cavity sketch" plane through (-0.3536, -0.3536, 0) normal (0.7071, 0.7071, 0) x axis (0, 0, 1)
  circle C1 centre (0, 0) radius 25.15
  dimension "d819" diameter C1 = 50.3 (= "mountOpening")
extrude "Extrude35" cut sketch "B Open Hub Cavity sketch" no distance stored
work_plane "WorkPlane20" ExtraOffset 0
sketch "B Four Mount Holes" plane through (-0.3536, -0.3536, 0) normal (0.7071, 0.7071, 0) x axis (0, 0, 1)
  circle C1 centre (22.6274, 22.6274) radius 2.15
  circle C2 centre (-22.6274, 22.6274) radius 2.15
  circle C3 centre (-22.6274, -22.6274) radius 2.15
  circle C4 centre (22.6274, -22.6274) radius 2.15
  point P1 (0, 0)
  point P2 (22.6274, 22.6274)
  point P3 (-22.6274, 22.6274)
  point P4 (-22.6274, -22.6274)
  point P5 (22.6274, -22.6274)
  dimension "d824" distance P1 P2 = 22.6274 (= "abs(mountCircle / ( 2 * sqrt(2) ))")
  dimension "d825" distance P1 P2 = 22.6274 (= "abs(mountCircle / ( 2 * sqrt(2) ))")
  dimension "d826" diameter C1 = 4.3 (= "m4Clearance")
  dimension "d827" distance P1 P3 = 22.6274 (= "abs(-mountCircle / ( 2 * sqrt(2) ))")
  dimension "d828" distance P1 P3 = 22.6274 (= "abs(mountCircle / ( 2 * sqrt(2) ))")
  dimension "d829" diameter C2 = 4.3 (= "m4Clearance")
  dimension "d830" distance P1 P4 = 22.6274 (= "abs(-mountCircle / ( 2 * sqrt(2) ))")
  dimension "d831" distance P1 P4 = 22.6274 (= "abs(-mountCircle / ( 2 * sqrt(2) ))")
  dimension "d832" diameter C3 = 4.3 (= "m4Clearance")
  dimension "d833" distance P1 P5 = 22.6274 (= "abs(mountCircle / ( 2 * sqrt(2) ))")
  dimension "d834" distance P1 P5 = 22.6274 (= "abs(-mountCircle / ( 2 * sqrt(2) ))")
  dimension "d835" diameter C4 = 4.3 (= "m4Clearance")
extrude "Extrude36" cut sketch "B Four Mount Holes" no distance stored
sketch "B M4 Nut Pocket 1" plane through (-0.3536, -0.3536, 0) normal (0.7071, 0.7071, 0) x axis (0, 0, 1)
  line L1 (24.7059, 26.2274) -> (26.7843, 22.6274)
  line L2 (20.549, 26.2274) -> (24.7059, 26.2274)
  line L3 (18.4705, 22.6274) -> (20.549, 26.2274)
  line L4 (20.549, 19.0274) -> (18.4705, 22.6274)
  line L5 (24.7059, 19.0274) -> (20.549, 19.0274)
  line L6 (26.7843, 22.6274) -> (24.7059, 19.0274)
  circle C1 centre (22.6274, 22.6274) radius 4.1569
  point P3 (26.7843, 22.6274)
  point P4 (24.7059, 26.2274)
  point P5 (20.549, 26.2274)
  point P6 (18.4705, 22.6274)
  point P7 (20.549, 19.0274)
  point P8 (24.7059, 19.0274)
  point P1 (0, 0)
  point P2 (22.6274, 22.6274)
  coincident C1 P3
  coincident C1 P4
  coincident C1 P5
  coincident C1 P6
  coincident C1 P7
  coincident C1 P8
  equal L1 L2
  equal L1 L3
  equal L1 L4
  equal L1 L5
  equal L1 L6
  horizontal L2
  dimension "d838" distance P1 P2 = 22.6274 (= "abs(mountCircle / ( 2 * sqrt(2) ))")
  dimension "d839" distance P1 P2 = 22.6274 (= "abs(mountCircle / ( 2 * sqrt(2) ))")
  dimension "d840" diameter C1 = 8.3138 (= "2 * ( nutAF ) / sqrt(3)")
extrude "Extrude37" cut sketch "B M4 Nut Pocket 1" profile of L1 L2 L3 L4 L5 L6 no distance stored
sketch "B M4 Nut Pocket 2" plane through (-0.3536, -0.3536, 0) normal (0.7071, 0.7071, 0) x axis (0, 0, 1)
  line L1 (-20.549, 26.2274) -> (-18.4705, 22.6274)
  line L2 (-24.7059, 26.2274) -> (-20.549, 26.2274)
  line L3 (-26.7843, 22.6274) -> (-24.7059, 26.2274)
  line L4 (-24.7059, 19.0274) -> (-26.7843, 22.6274)
  line L5 (-20.549, 19.0274) -> (-24.7059, 19.0274)
  line L6 (-18.4705, 22.6274) -> (-20.549, 19.0274)
  circle C1 centre (-22.6274, 22.6274) radius 4.1569
  point P3 (-18.4705, 22.6274)
  point P4 (-20.549, 26.2274)
  point P5 (-24.7059, 26.2274)
  point P6 (-26.7843, 22.6274)
  point P7 (-24.7059, 19.0274)
  point P8 (-20.549, 19.0274)
  point P1 (0, 0)
  point P2 (-22.6274, 22.6274)
  coincident C1 P3
  coincident C1 P4
  coincident C1 P5
  coincident C1 P6
  coincident C1 P7
  coincident C1 P8
  equal L1 L2
  equal L1 L3
  equal L1 L4
  equal L1 L5
  equal L1 L6
  horizontal L2
  dimension "d843" distance P1 P2 = 22.6274 (= "abs(-mountCircle / ( 2 * sqrt(2) ))")
  dimension "d844" distance P1 P2 = 22.6274 (= "abs(mountCircle / ( 2 * sqrt(2) ))")
  dimension "d845" diameter C1 = 8.3138 (= "2 * ( nutAF ) / sqrt(3)")
extrude "Extrude38" cut sketch "B M4 Nut Pocket 2" profile of L1 L2 L3 L4 L5 L6 no distance stored
sketch "B M4 Nut Pocket 3" plane through (-0.3536, -0.3536, 0) normal (0.7071, 0.7071, 0) x axis (0, 0, 1)
  line L1 (-20.549, -19.0274) -> (-18.4705, -22.6274)
  line L2 (-24.7059, -19.0274) -> (-20.549, -19.0274)
  line L3 (-26.7843, -22.6274) -> (-24.7059, -19.0274)
  line L4 (-24.7059, -26.2274) -> (-26.7843, -22.6274)
  line L5 (-20.549, -26.2274) -> (-24.7059, -26.2274)
  line L6 (-18.4705, -22.6274) -> (-20.549, -26.2274)
  circle C1 centre (-22.6274, -22.6274) radius 4.1569
  point P3 (-18.4705, -22.6274)
  point P4 (-20.549, -19.0274)
  point P5 (-24.7059, -19.0274)
  point P6 (-26.7843, -22.6274)
  point P7 (-24.7059, -26.2274)
  point P8 (-20.549, -26.2274)
  point P1 (0, 0)
  point P2 (-22.6274, -22.6274)
  coincident C1 P3
  coincident C1 P4
  coincident C1 P5
  coincident C1 P6
  coincident C1 P7
  coincident C1 P8
  equal L1 L2
  equal L1 L3
  equal L1 L4
  equal L1 L5
  equal L1 L6
  horizontal L2
  dimension "d848" distance P1 P2 = 22.6274 (= "abs(-mountCircle / ( 2 * sqrt(2) ))")
  dimension "d849" distance P1 P2 = 22.6274 (= "abs(-mountCircle / ( 2 * sqrt(2) ))")
  dimension "d850" diameter C1 = 8.3138 (= "2 * ( nutAF ) / sqrt(3)")
extrude "Extrude39" cut sketch "B M4 Nut Pocket 3" profile of L1 L2 L3 L4 L5 L6 no distance stored
sketch "B M4 Nut Pocket 4" plane through (-0.3536, -0.3536, 0) normal (0.7071, 0.7071, 0) x axis (0, 0, 1)
  line L1 (24.7059, -19.0274) -> (26.7843, -22.6274)
  line L2 (20.549, -19.0274) -> (24.7059, -19.0274)
  line L3 (18.4705, -22.6274) -> (20.549, -19.0274)
  line L4 (20.549, -26.2274) -> (18.4705, -22.6274)
  line L5 (24.7059, -26.2274) -> (20.549, -26.2274)
  line L6 (26.7843, -22.6274) -> (24.7059, -26.2274)
  circle C1 centre (22.6274, -22.6274) radius 4.1569
  point P3 (26.7843, -22.6274)
  point P4 (24.7059, -19.0274)
  point P5 (20.549, -19.0274)
  point P6 (18.4705, -22.6274)
  point P7 (20.549, -26.2274)
  point P8 (24.7059, -26.2274)
  point P1 (0, 0)
  point P2 (22.6274, -22.6274)
  coincident C1 P3
  coincident C1 P4
  coincident C1 P5
  coincident C1 P6
  coincident C1 P7
  coincident C1 P8
  equal L1 L2
  equal L1 L3
  equal L1 L4
  equal L1 L5
  equal L1 L6
  horizontal L2
  dimension "d853" distance P1 P2 = 22.6274 (= "abs(mountCircle / ( 2 * sqrt(2) ))")
  dimension "d854" distance P1 P2 = 22.6274 (= "abs(-mountCircle / ( 2 * sqrt(2) ))")
  dimension "d855" diameter C1 = 8.3138 (= "2 * ( nutAF ) / sqrt(3)")
extrude "Extrude40" cut sketch "B M4 Nut Pocket 4" profile of L1 L2 L3 L4 L5 L6 no distance stored
sketch "B Hub Service Slots" plane through (0, 0, 0) normal (0, 0, 1) x axis (1, 0, 0)
  line L1 (-30.4056, -12.0208) -> (-14.8492, 3.5355)
  line L2 (-12.0208, -30.4056) -> (-30.4056, -12.0208)
  line L3 (3.5355, -14.8492) -> (-12.0208, -30.4056)
  line L4 (-14.8492, 3.5355) -> (3.5355, -14.8492)
  point P1 (0, 0)
  point P2 (-14.8492, 3.5355)
  point P3 (-30.4056, -12.0208)
  point P4 (-12.0208, -30.4056)
  point P5 (3.5355, -14.8492)
  dimension "d858" distance P1 P2 = 14.8492 (= "abs(( -8 mm - 13 mm ) / sqrt(2))")
  dimension "d859" distance P1 P2 = 3.5355 (= "abs(( -8 mm + 13 mm ) / sqrt(2))")
  dimension "d860" distance P1 P3 = 30.4056 (= "abs(( -30 mm - 13 mm ) / sqrt(2))")
  dimension "d861" distance P1 P3 = 12.0208 (= "abs(( -30 mm + 13 mm ) / sqrt(2))")
  dimension "d862" distance P1 P4 = 12.0208 (= "abs(( -30 mm + 13 mm ) / sqrt(2))")
  dimension "d863" distance P1 P4 = 30.4056 (= "abs(( -30 mm - 13 mm ) / sqrt(2))")
  dimension "d864" distance P1 P5 = 3.5355 (= "abs(( -8 mm + 13 mm ) / sqrt(2))")
  dimension "d865" distance P1 P5 = 14.8492 (= "abs(( -8 mm - 13 mm ) / sqrt(2))")
extrude "Extrude41" cut sketch "B Hub Service Slots" distance 76 (= "mountOD")
chamfer "Chamfer2" distance 0.3 (= "bedRelief")
chamfer "Chamfer3" distance 0.5 (= "tubeCornerChamfer")
chamfer "Chamfer4" sketch "A Facet 135 Triangle 1" distance 0.3 (= "tubeRimChamfer")
work_plane "WorkPlane25" RotateAngle 0 ExtraOffset 0
work_plane "WorkPlane26" AlongDistance 75 (= "bodyWidth / 2") ExtraOffset 0
sketch "A End Cord Port" plane through (0, 0, 75) normal (0, 0, 1) x axis (1, 0, 0)
  line L1 (125, 0) -> (0, 0)
  circle C1 centre (125, 0) radius 2.25
  point P1 (0, 0)
  point P2 (125, 0)
  horizontal L1
  dimension "d875" distance P1 P2 = 125 (= "abs(( 1 ) * ( ( 1 ) * cordStation ) + ( 0 ) * ( 0 mm ))")
  dimension "d876" diameter C1 = 4.5
extrude "Extrude40" cut sketch "A End Cord Port" profile of C1 no distance stored
chamfer "Chamfer5" distance 0.3 (= "bedRelief")
work_plane "WorkPlane27" RotateAngle 180 ExtraOffset 0
work_plane "WorkPlane28" AlongDistance 75 (= "bodyWidth / 2") ExtraOffset 0
sketch "A End Cord Port (1)" plane through (0, 0, -75) normal (0, 0, -1) x axis (-1, 0, 0)
  line L1 (-125, 0) -> (0, 0)
  circle C1 centre (-125, 0) radius 2.25
  point P1 (0, 0)
  point P2 (-125, 0)
  horizontal L1
  dimension "d884" distance P1 P2 = 125 (= "abs(( -1 ) * ( ( 1 ) * cordStation ) + ( 0 ) * ( 0 mm ))")
  dimension "d885" diameter C1 = 4.5
extrude "Extrude41" cut sketch "A End Cord Port (1)" profile of C1 no distance stored
chamfer "Chamfer6" distance 0.3 (= "bedRelief")
chamfer "Chamfer1" distance 0.3 (= "bedRelief")
chamfer "Chamfer2" distance 0.5 (= "tubeCornerChamfer")
chamfer "Chamfer3" sketch "A Facet 135 Triangle 1" distance 0.3 (= "tubeRimChamfer")
work_plane "WorkPlane21" RotateAngle 0 ExtraOffset 0
work_plane "WorkPlane22" AlongDistance 75 (= "bodyWidth / 2") ExtraOffset 0
sketch "B End Cord Port" plane through (0, 0, 75) normal (0, 0, 1) x axis (1, 0, 0)
  line L1 (-125, 0) -> (0, 0)
  circle C1 centre (-125, 0) radius 2.25
  point P1 (0, 0)
  point P2 (-125, 0)
  horizontal L1
  dimension "d896" distance P1 P2 = 125 (= "abs(( 1 ) * ( ( -1 ) * cordStation ) + ( 0 ) * ( 0 mm ))")
  dimension "d897" diameter C1 = 4.5
extrude "Extrude42" cut sketch "B End Cord Port" profile of C1 no distance stored
chamfer "Chamfer4" distance 0.3 (= "bedRelief")
work_plane "WorkPlane23" RotateAngle 180 ExtraOffset 0
work_plane "WorkPlane24" AlongDistance 75 (= "bodyWidth / 2") ExtraOffset 0
sketch "B End Cord Port (1)" plane through (0, 0, -75) normal (0, 0, -1) x axis (-1, 0, 0)
  line L1 (125, 0) -> (0, 0)
  circle C1 centre (125, 0) radius 2.25
  point P1 (0, 0)
  point P2 (125, 0)
  horizontal L1
  dimension "d905" distance P1 P2 = 125 (= "abs(( -1 ) * ( ( -1 ) * cordStation ) + ( 0 ) * ( 0 mm ))")
  dimension "d906" diameter C1 = 4.5
extrude "Extrude43" cut sketch "B End Cord Port (1)" profile of C1 no distance stored
chamfer "Chamfer5" distance 0.3 (= "bedRelief")
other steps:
base_feature "Base Feature1" bodies "A Housing print"
base_feature "Base Feature1" bodies "B Moving Body print"
create_component "CreateComponent1"
reparent_decal "ReparentDecal1"
remove_body "RemoveBody1"
create_component "CreateComponent2"
reparent_decal "ReparentDecal2"
remove_body "RemoveBody2"
named bodies: "A Housing print", "B Moving Body print"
